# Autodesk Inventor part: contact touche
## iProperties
Shininess: 21.0
Length Units: 11269
Angle Units: 11279
Time Units: 11290
Mass Units: 11283
Length Display Precision: 3
Angle Display Precision: 2
Created: 2002-03
Part Number: contact touche
Material: Par défaut
Document SubType Name: Modélisation
Designer: User
Density: 0.0
Volumn: 0.0
Area: 0.0
PropertySet Name: Model Information
Control State: 0
Master: False
Checked Out: False
Author: User
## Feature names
1. Extrusion1
2. Extrusion2
3. Extrusion3
